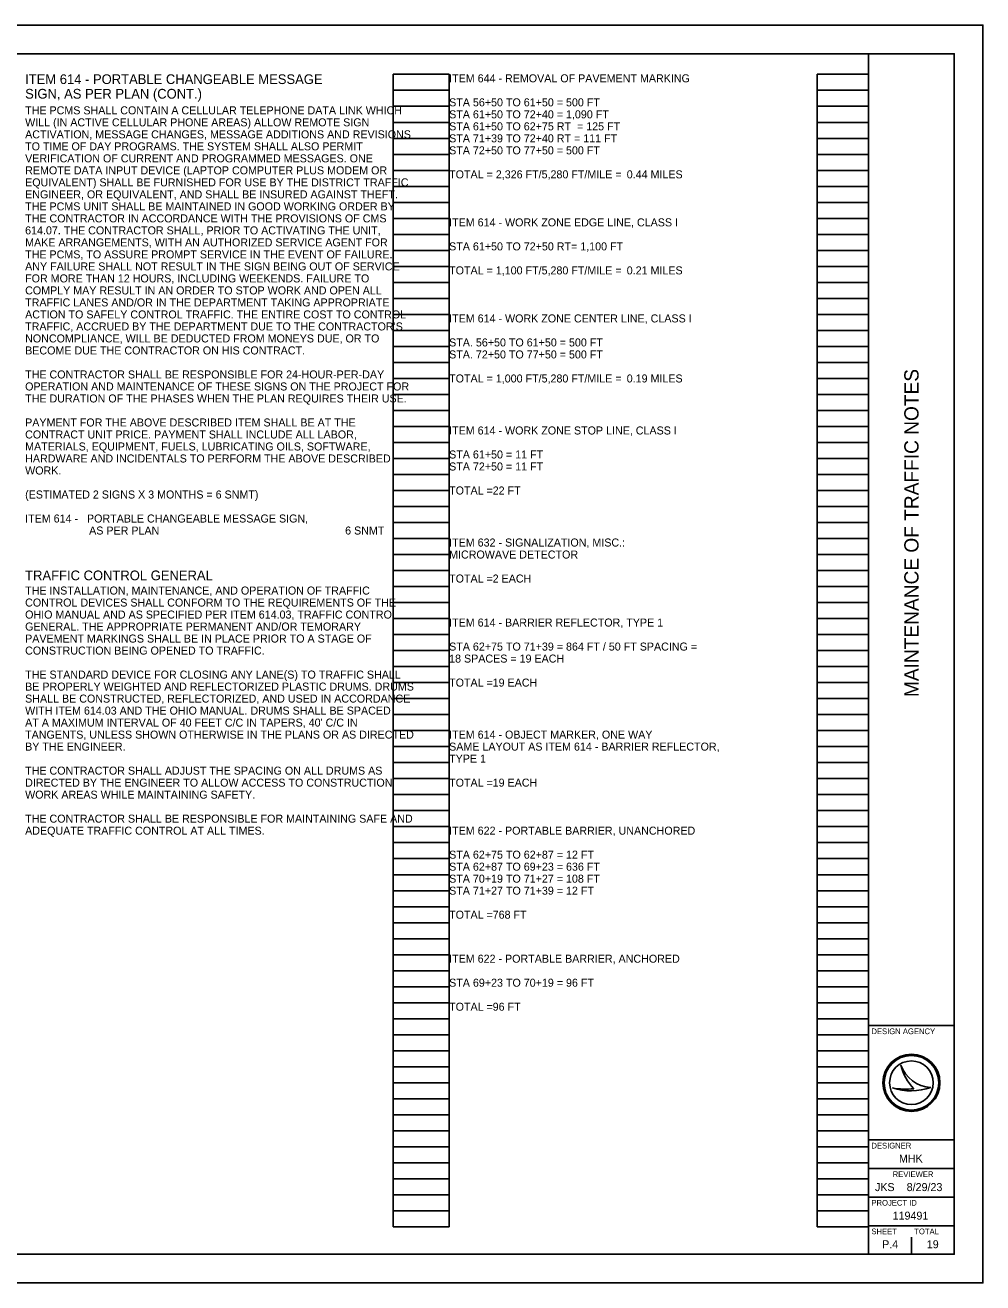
# Model space of a CAD drawing. Extents: x 0 to 34, y 0 to 22.
# Drawn here: x 17.24 to 34, y 0 to 22 of the extents above; entities that cross this region are included whole.
import ezdxf

# ---------------------------------------------------------------- set-up
doc = ezdxf.new("R2010")
doc.units = 0
for name, color, linetype in [('SH_Border', 7, 'Continuous'), ('SH_Cut_Line', 7, 'Continuous'), ('SH_Data', 7, 'Continuous'), ('SH_Text', 7, 'Continuous')]:
    doc.layers.add(name, color=color, linetype=linetype)

msp = doc.modelspace()

# ---------------------------------------------------------------- linework, layer by layer
at = {"layer": 'SH_Border'}
for p, q in [((32, 0.5), (32, 21.5)), ((32, 4.5), (33.5, 4.5)), ((32, 2.5), (33.5, 2.5)), ((32, 2), (33.5, 2)), ((32, 1.5), (33.5, 1.5)), ((32, 1), (33.5, 1))]:
    msp.add_line(p, q, dxfattribs=at)
msp.add_lwpolyline([(1.5, 21.5), (33.5, 21.5), (33.5, 0.5), (1.5, 0.5)], close=True, dxfattribs=at)
at = {"layer": 'SH_Cut_Line'}
msp.add_lwpolyline([(0, 0), (34, 0), (34, 22), (0, 22)], close=True, dxfattribs=at)
at = {"layer": 'SH_Data'}
for p, q in [((23.68, 0.98), (23.68, 21.14)), ((23.68, 21.14), (24.66, 21.14)), ((24.66, 0.98), (24.66, 21.14)), ((31.1, 0.98), (31.1, 21.14)), ((31.1, 21.14), (32, 21.14)), ((32, 0.98), (32, 21.14)), ((23.68, 20.86), (24.66, 20.86)), ((31.1, 20.86), (32, 20.86)), ((23.68, 20.58), (24.66, 20.58)), ((31.1, 20.58), (32, 20.58)), ((23.68, 20.3), (24.66, 20.3)), ((31.1, 20.3), (32, 20.3)), ((23.68, 20.02), (24.66, 20.02)), ((31.1, 20.02), (32, 20.02)), ((23.68, 19.74), (24.66, 19.74)), ((31.1, 19.74), (32, 19.74)), ((23.68, 19.46), (24.66, 19.46)), ((31.1, 19.46), (32, 19.46)), ((23.68, 19.18), (24.66, 19.18)), ((31.1, 19.18), (32, 19.18)), ((23.68, 18.9), (24.66, 18.9)), ((31.1, 18.9), (32, 18.9)), ((23.68, 18.62), (24.66, 18.62)), ((31.1, 18.62), (32, 18.62)), ((23.68, 18.34), (24.66, 18.34)), ((31.1, 18.34), (32, 18.34)), ((23.68, 18.06), (24.66, 18.06)), ((31.1, 18.06), (32, 18.06)), ((23.68, 17.78), (24.66, 17.78)), ((31.1, 17.78), (32, 17.78)), ((23.68, 17.5), (24.66, 17.5)), ((31.1, 17.5), (32, 17.5)), ((23.68, 17.22), (24.66, 17.22)), ((31.1, 17.22), (32, 17.22)), ((23.68, 16.94), (24.66, 16.94)), ((31.1, 16.94), (32, 16.94)), ((23.68, 16.66), (24.66, 16.66)), ((31.1, 16.66), (32, 16.66)), ((23.68, 16.38), (24.66, 16.38)), ((31.1, 16.38), (32, 16.38)), ((23.68, 16.1), (24.66, 16.1)), ((31.1, 16.1), (32, 16.1)), ((23.68, 15.82), (24.66, 15.82)), ((31.1, 15.82), (32, 15.82)), ((23.68, 15.54), (24.66, 15.54)), ((31.1, 15.54), (32, 15.54)), ((23.68, 15.26), (24.66, 15.26)), ((31.1, 15.26), (32, 15.26)), ((23.68, 14.98), (24.66, 14.98)), ((31.1, 14.98), (32, 14.98)), ((23.68, 14.7), (24.66, 14.7)), ((31.1, 14.7), (32, 14.7)), ((23.68, 14.42), (24.66, 14.42)), ((31.1, 14.42), (32, 14.42)), ((23.68, 14.14), (24.66, 14.14)), ((31.1, 14.14), (32, 14.14)), ((23.68, 13.86), (24.66, 13.86)), ((31.1, 13.86), (32, 13.86)), ((23.68, 13.58), (24.66, 13.58)), ((31.1, 13.58), (32, 13.58)), ((23.68, 13.3), (24.66, 13.3)), ((31.1, 13.3), (32, 13.3)), ((23.68, 13.02), (24.66, 13.02)), ((31.1, 13.02), (32, 13.02)), ((23.68, 12.74), (24.66, 12.74)), ((31.1, 12.74), (32, 12.74)), ((23.68, 12.46), (24.66, 12.46)), ((31.1, 12.46), (32, 12.46)), ((23.68, 12.18), (24.66, 12.18)), ((31.1, 12.18), (32, 12.18)), ((23.68, 11.9), (24.66, 11.9)), ((31.1, 11.9), (32, 11.9)), ((23.68, 11.62), (24.66, 11.62)), ((31.1, 11.62), (32, 11.62)), ((23.68, 11.34), (24.66, 11.34)), ((31.1, 11.34), (32, 11.34)), ((23.68, 11.06), (24.66, 11.06)), ((31.1, 11.06), (32, 11.06)), ((23.68, 10.78), (24.66, 10.78)), ((31.1, 10.78), (32, 10.78)), ((23.68, 10.5), (24.66, 10.5)), ((31.1, 10.5), (32, 10.5)), ((23.68, 10.22), (24.66, 10.22)), ((31.1, 10.22), (32, 10.22)), ((23.68, 9.94), (24.66, 9.94)), ((31.1, 9.94), (32, 9.94)), ((23.68, 9.66), (24.66, 9.66)), ((31.1, 9.66), (32, 9.66)), ((23.68, 9.38), (24.66, 9.38)), ((31.1, 9.38), (32, 9.38)), ((23.68, 9.1), (24.66, 9.1)), ((31.1, 9.1), (32, 9.1)), ((23.68, 8.82), (24.66, 8.82)), ((31.1, 8.82), (32, 8.82)), ((23.68, 8.54), (24.66, 8.54)), ((31.1, 8.54), (32, 8.54)), ((23.68, 8.26), (24.66, 8.26)), ((31.1, 8.26), (32, 8.26)), ((23.68, 7.98), (24.66, 7.98)), ((31.1, 7.98), (32, 7.98)), ((23.68, 7.7), (24.66, 7.7)), ((31.1, 7.7), (32, 7.7)), ((23.68, 7.42), (24.66, 7.42)), ((31.1, 7.42), (32, 7.42)), ((23.68, 7.14), (24.66, 7.14)), ((31.1, 7.14), (32, 7.14)), ((23.68, 6.86), (24.66, 6.86)), ((31.1, 6.86), (32, 6.86)), ((23.68, 6.58), (24.66, 6.58)), ((31.1, 6.58), (32, 6.58)), ((23.68, 6.3), (24.66, 6.3)), ((31.1, 6.3), (32, 6.3)), ((23.68, 6.02), (24.66, 6.02)), ((31.1, 6.02), (32, 6.02)), ((23.68, 5.74), (24.66, 5.74)), ((31.1, 5.74), (32, 5.74)), ((23.68, 5.46), (24.66, 5.46)), ((31.1, 5.46), (32, 5.46)), ((23.68, 5.18), (24.66, 5.18)), ((31.1, 5.18), (32, 5.18)), ((23.68, 4.9), (24.66, 4.9)), ((31.1, 4.9), (32, 4.9)), ((23.68, 4.62), (24.66, 4.62)), ((31.1, 4.62), (32, 4.62)), ((23.68, 4.34), (24.66, 4.34)), ((31.1, 4.34), (32, 4.34)), ((23.68, 4.06), (24.66, 4.06)), ((31.1, 4.06), (32, 4.06)), ((23.68, 3.78), (24.66, 3.78)), ((31.1, 3.78), (32, 3.78)), ((32.567, 3.81), (32.567, 3.81)), ((23.68, 3.5), (24.66, 3.5)), ((31.1, 3.5), (32, 3.5)), ((32.417, 3.41), (32.417, 3.41)), ((32.75, 3.5), (32.75, 3.5)), ((33.087, 3.419), (33.087, 3.419)), ((23.68, 3.22), (24.66, 3.22)), ((31.1, 3.22), (32, 3.22)), ((23.68, 2.94), (24.66, 2.94)), ((31.1, 2.94), (32, 2.94)), ((23.68, 2.66), (24.66, 2.66)), ((31.1, 2.66), (32, 2.66)), ((23.68, 2.38), (24.66, 2.38)), ((31.1, 2.38), (32, 2.38)), ((23.68, 2.1), (24.66, 2.1)), ((31.1, 2.1), (32, 2.1)), ((23.68, 1.82), (24.66, 1.82)), ((31.1, 1.82), (32, 1.82)), ((23.68, 1.54), (24.66, 1.54)), ((31.1, 1.54), (32, 1.54)), ((23.68, 1.26), (24.66, 1.26)), ((31.1, 1.26), (32, 1.26)), ((23.68, 0.98), (24.66, 0.98)), ((31.1, 0.98), (32, 0.98)), ((32.375, 0.675), (32.375, 0.675)), ((32.75, 0.5), (32.75, 0.8))]:
    msp.add_line(p, q, dxfattribs=at)
for radius in [0.5, 0.477, 0.477, 0.382]:
    msp.add_circle((32.75, 3.5), radius, dxfattribs=at)
for centre, radius, start, end in [((33.116, 3.998), 0.58, 198.9257, 198.9319), ((33.347, 3.97), 0.796, 191.6379, 191.6421), ((33.116, 3.998), 0.58, 198.9319, 267.1657), ((33.347, 3.97), 0.796, 191.6421, 226.0947), ((32.739, 4.37), 1.013, 251.4576, 290.0832), ((32.648, 4.654), 1.266, 259.4964, 259.4995), ((32.739, 4.37), 1.013, 251.4527, 251.4576), ((32.648, 4.654), 1.266, 259.4995, 276.6672)]:
    msp.add_arc(centre, radius, start, end, dxfattribs=at)

# ---------------------------------------------------------------- texts
for s, height, p in [('ITEM 644 - REMOVAL OF PAVEMENT MARKING', 0.14, (24.66, 21)), ('STA 56+50 TO 61+50 = 500 FT', 0.14, (24.66, 20.58)), ('STA 61+50 TO 72+40 = 1,090 FT', 0.14, (24.66, 20.37)), ('STA 61+50 TO 62+75 RT  = 125 FT', 0.14, (24.66, 20.16)), ('STA 71+39 TO 72+40 RT = 111 FT', 0.14, (24.66, 19.95)), ('STA 72+50 TO 77+50 = 500 FT', 0.14, (24.66, 19.74)), ('TOTAL = 2,326 FT/5,280 FT/MILE = ', 0.14, (24.66, 19.32)), ('0.44 MILES', 0.14, (27.768, 19.32)), ('ITEM 614 - WORK ZONE EDGE LINE, CLASS I', 0.14, (24.66, 18.48)), ('STA 61+50 TO 72+50 RT= 1,100 FT', 0.14, (24.66, 18.06)), ('TOTAL = 1,100 FT/5,280 FT/MILE = ', 0.14, (24.66, 17.64)), ('0.21 MILES', 0.14, (27.768, 17.64)), ('ITEM 614 - WORK ZONE CENTER LINE, CLASS I', 0.14, (24.66, 16.8)), ('STA. 56+50 TO 61+50 = 500 FT', 0.14, (24.66, 16.38)), ('STA. 72+50 TO 77+50 = 500 FT', 0.14, (24.66, 16.17)), ('TOTAL = 1,000 FT/5,280 FT/MILE = ', 0.14, (24.66, 15.75)), ('0.19 MILES', 0.14, (27.768, 15.75)), ('ITEM 614 - WORK ZONE STOP LINE, CLASS I', 0.14, (24.66, 14.84)), ('STA 61+50 = 11 FT', 0.14, (24.66, 14.42)), ('STA 72+50 = 11 FT', 0.14, (24.66, 14.21)), ('TOTAL = ', 0.14, (24.66, 13.79)), ('22 FT', 0.14, (25.422, 13.79)), ('ITEM 632 - SIGNALIZATION, MISC.: ', 0.14, (24.66, 12.88)), ('MICROWAVE DETECTOR', 0.14, (24.66, 12.67)), ('TOTAL = ', 0.14, (24.66, 12.25)), ('2 EACH', 0.14, (25.422, 12.25)), ('ITEM 614 - BARRIER REFLECTOR, TYPE 1', 0.14, (24.66, 11.48)), ('STA 62+75 TO 71+39 = 864 FT / 50 FT SPACING = ', 0.14, (24.66, 11.06)), ('18 SPACES = 19 EACH', 0.14, (24.66, 10.85)), ('TOTAL = ', 0.14, (24.66, 10.43)), ('19 EACH', 0.14, (25.422, 10.43)), ('ITEM 614 - OBJECT MARKER, ONE WAY', 0.14, (24.66, 9.52)), ('TYPE 1', 0.14, (24.66, 9.1)), ('SAME LAYOUT AS ITEM 614 - BARRIER REFLECTOR, ', 0.14, (24.66, 9.31)), ('TOTAL = ', 0.14, (24.66, 8.68)), ('19 EACH', 0.14, (25.422, 8.68)), ('ITEM 622 - PORTABLE BARRIER, UNANCHORED', 0.14, (24.66, 7.84)), ('STA 62+75 TO 62+87 = 12 FT', 0.14, (24.66, 7.42)), ('STA 62+87 TO 69+23 = 636 FT', 0.14, (24.66, 7.21)), ('STA 70+19 TO 71+27 = 108 FT', 0.14, (24.66, 7)), ('STA 71+27 TO 71+39 = 12 FT', 0.14, (24.66, 6.79)), ('TOTAL = ', 0.14, (24.66, 6.37)), ('768 FT', 0.14, (25.422, 6.37)), ('ITEM 622 - PORTABLE BARRIER, ANCHORED', 0.14, (24.66, 5.6)), ('STA 69+23 TO 70+19 = 96 FT', 0.14, (24.66, 5.18)), ('TOTAL = ', 0.14, (24.66, 4.76)), ('96 FT', 0.14, (25.422, 4.76)), ('DESIGN AGENCY', 0.1, (32.05, 4.35)), ('DESIGNER', 0.1, (32.05, 2.35)), ('MHK', 0.14, (32.532, 2.105)), ('REVIEWER', 0.1, (32.422, 1.85)), ('JKS', 0.14, (32.112, 1.605)), ('8/29/23', 0.14, (32.667, 1.605)), ('PROJECT ID', 0.1, (32.05, 1.35)), ('119491', 0.14, (32.421, 1.105)), ('SHEET', 0.1, (32.05, 0.85)), ('TOTAL', 0.1, (32.8, 0.85)), ('P.4', 0.14, (32.237, 0.605)), ('19', 0.14, (33.019, 0.605))]:
    msp.add_text(s, height=height, dxfattribs=at).set_placement(p)
msp.add_text('MAINTENANCE OF TRAFFIC NOTES', height=0.25, rotation=90, dxfattribs=at).set_placement((32.875, 10.247))
at = {"layer": 'SH_Text'}
for s, height, p in [('ITEM 614 - PORTABLE CHANGEABLE MESSAGE', 0.17, (17.24, 20.97)), ('SIGN, AS PER PLAN (CONT.)', 0.17, (17.24, 20.715)), ('THE PCMS SHALL CONTAIN A CELLULAR TELEPHONE DATA LINK WHICH ', 0.14, (17.24, 20.44)), ('WILL (IN ACTIVE CELLULAR PHONE AREAS) ALLOW REMOTE SIGN ', 0.14, (17.24, 20.23)), ('ACTIVATION, MESSAGE CHANGES, MESSAGE ADDITIONS AND REVISIONS ', 0.14, (17.24, 20.02)), ('TO TIME OF DAY PROGRAMS. THE SYSTEM SHALL ALSO PERMIT ', 0.14, (17.24, 19.81)), ('VERIFICATION OF CURRENT AND PROGRAMMED MESSAGES. ONE ', 0.14, (17.24, 19.6)), ('REMOTE DATA INPUT DEVICE (LAPTOP COMPUTER PLUS MODEM OR ', 0.14, (17.24, 19.39)), ('EQUIVALENT) SHALL BE FURNISHED FOR USE BY THE DISTRICT TRAFFIC ', 0.14, (17.24, 19.18)), ('ENGINEER, OR EQUIVALENT, AND SHALL BE INSURED AGAINST THEFT. ', 0.14, (17.24, 18.97)), ('THE PCMS UNIT SHALL BE MAINTAINED IN GOOD WORKING ORDER BY ', 0.14, (17.24, 18.76)), ('THE CONTRACTOR IN ACCORDANCE WITH THE PROVISIONS OF CMS ', 0.14, (17.24, 18.55)), ('614.07. THE CONTRACTOR SHALL, PRIOR TO ACTIVATING THE UNIT, ', 0.14, (17.24, 18.34)), ('MAKE ARRANGEMENTS, WITH AN AUTHORIZED SERVICE AGENT FOR ', 0.14, (17.24, 18.13)), ('THE PCMS, TO ASSURE PROMPT SERVICE IN THE EVENT OF FAILURE. ', 0.14, (17.24, 17.92)), ('ANY FAILURE SHALL NOT RESULT IN THE SIGN BEING OUT OF SERVICE ', 0.14, (17.24, 17.71)), ('FOR MORE THAN 12 HOURS, INCLUDING WEEKENDS. FAILURE TO ', 0.14, (17.24, 17.5)), ('COMPLY MAY RESULT IN AN ORDER TO STOP WORK AND OPEN ALL ', 0.14, (17.24, 17.29)), ('TRAFFIC LANES AND/OR IN THE DEPARTMENT TAKING APPROPRIATE ', 0.14, (17.24, 17.08)), ('ACTION TO SAFELY CONTROL TRAFFIC. THE ENTIRE COST TO CONTROL ', 0.14, (17.24, 16.87)), ("TRAFFIC, ACCRUED BY THE DEPARTMENT DUE TO THE CONTRACTOR'S ", 0.14, (17.24, 16.66)), ('NONCOMPLIANCE, WILL BE DEDUCTED FROM MONEYS DUE, OR TO ', 0.14, (17.24, 16.45)), ('BECOME DUE THE CONTRACTOR ON HIS CONTRACT.', 0.14, (17.24, 16.24)), ('THE CONTRACTOR SHALL BE RESPONSIBLE FOR 24-HOUR-PER-DAY ', 0.14, (17.24, 15.82)), ('OPERATION AND MAINTENANCE OF THESE SIGNS ON THE PROJECT FOR ', 0.14, (17.24, 15.61)), ('THE DURATION OF THE PHASES WHEN THE PLAN REQUIRES THEIR USE.', 0.14, (17.24, 15.4)), ('PAYMENT FOR THE ABOVE DESCRIBED ITEM SHALL BE AT THE ', 0.14, (17.24, 14.98)), ('CONTRACT UNIT PRICE. PAYMENT SHALL INCLUDE ALL LABOR, ', 0.14, (17.24, 14.77)), ('MATERIALS, EQUIPMENT, FUELS, LUBRICATING OILS, SOFTWARE, ', 0.14, (17.24, 14.56)), ('HARDWARE AND INCIDENTALS TO PERFORM THE ABOVE DESCRIBED ', 0.14, (17.24, 14.35)), ('WORK.', 0.14, (17.24, 14.14)), ('(ESTIMATED 2 SIGNS X 3 MONTHS = 6 SNMT)', 0.14, (17.24, 13.72)), ('ITEM 614 -   PORTABLE CHANGEABLE MESSAGE SIGN,', 0.14, (17.24, 13.3)), ('AS PER PLAN', 0.14, (18.36, 13.09)), ('6 SNMT', 0.14, (22.84, 13.09)), ('TRAFFIC CONTROL GENERAL', 0.17, (17.24, 12.29)), ('THE INSTALLATION, MAINTENANCE, AND OPERATION OF TRAFFIC ', 0.14, (17.24, 12.04)), ('CONTROL DEVICES SHALL CONFORM TO THE REQUIREMENTS OF THE ', 0.14, (17.24, 11.83)), ('OHIO MANUAL AND AS SPECIFIED PER ITEM 614.03, TRAFFIC CONTROL ', 0.14, (17.24, 11.62)), ('GENERAL. THE APPROPRIATE PERMANENT AND/OR TEMORARY ', 0.14, (17.24, 11.41)), ('PAVEMENT MARKINGS SHALL BE IN PLACE PRIOR TO A STAGE OF ', 0.14, (17.24, 11.2)), ('CONSTRUCTION BEING OPENED TO TRAFFIC.', 0.14, (17.24, 10.99)), ('THE STANDARD DEVICE FOR CLOSING ANY LANE(S) TO TRAFFIC SHALL ', 0.14, (17.24, 10.57)), ('BE PROPERLY WEIGHTED AND REFLECTORIZED PLASTIC DRUMS. DRUMS ', 0.14, (17.24, 10.36)), ('SHALL BE CONSTRUCTED, REFLECTORIZED, AND USED IN ACCORDANCE ', 0.14, (17.24, 10.15)), ('WITH ITEM 614.03 AND THE OHIO MANUAL. DRUMS SHALL BE SPACED ', 0.14, (17.24, 9.94)), ("AT A MAXIMUM INTERVAL OF 40 FEET C/C IN TAPERS, 40' C/C IN ", 0.14, (17.24, 9.73)), ('TANGENTS, UNLESS SHOWN OTHERWISE IN THE PLANS OR AS DIRECTED ', 0.14, (17.24, 9.52)), ('BY THE ENGINEER.', 0.14, (17.24, 9.31)), ('THE CONTRACTOR SHALL ADJUST THE SPACING ON ALL DRUMS AS ', 0.14, (17.24, 8.89)), ('DIRECTED BY THE ENGINEER TO ALLOW ACCESS TO CONSTRUCTION ', 0.14, (17.24, 8.68)), ('WORK AREAS WHILE MAINTAINING SAFETY.', 0.14, (17.24, 8.47)), ('THE CONTRACTOR SHALL BE RESPONSIBLE FOR MAINTAINING SAFE AND ', 0.14, (17.24, 8.05)), ('ADEQUATE TRAFFIC CONTROL AT ALL TIMES.', 0.14, (17.24, 7.84))]:
    msp.add_text(s, height=height, dxfattribs=at).set_placement(p)

doc.saveas('drawing.dxf')
